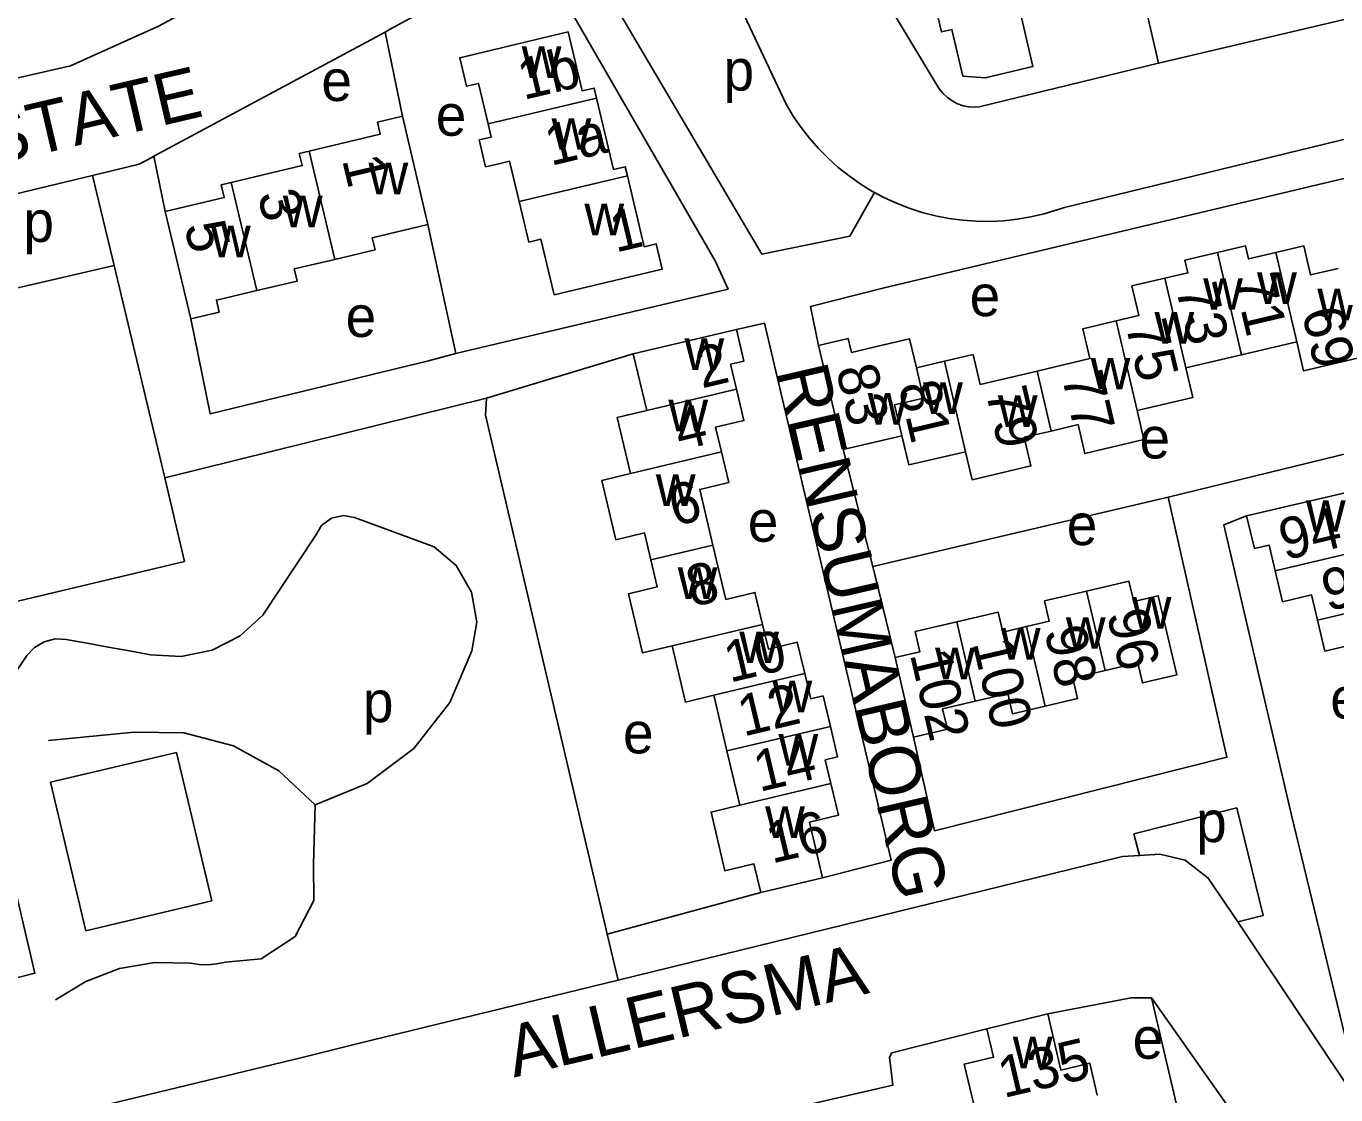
# Model space of a CAD drawing. Extents: x 157646 to 159241, y 379213 to 381217.
# Drawn here: x 158754.8 to 158882.3, y 380482.4 to 380586.3 of the extents above; entities that cross this region are included whole.
import ezdxf

# ---------------------------------------------------------------- set-up
doc = ezdxf.new("R2010")
doc.units = 0
for name, color, linetype in [('BLT_Basislijn', 7, 'Continuous'), ('BLT_Bebouwing', 7, 'Continuous'), ('BLT_Centroide', 7, 'Continuous'), ('BLT_Huisnummer', 7, 'Continuous'), ('BLT_Huisnummer_ tussenligend', 7, 'Continuous'), ('BLT_Onderverdeling_panden', 7, 'Continuous'), ('BLT_Straatnaam', 7, 'Continuous')]:
    doc.layers.add(name, color=color, linetype=linetype)

msp = doc.modelspace()

# ---------------------------------------------------------------- linework, layer by layer
at = {"layer": 'BLT_Basislijn'}
for p, q in [((158828.79, 380578.74), (158821.62, 380593.98)), ((158865.01, 380582.73), (158887.56, 380588.05)), ((158789.75, 380585.76), (158767.26, 380573.68)), ((158789.75, 380585.76), (158791.44, 380577.57)), ((158865.01, 380582.73), (158847.58, 380578.48)), ((158908.94, 380581.61), (158855.86, 380568.7)), ((158767.26, 380573.68), (158768.36, 380568.31)), ((158761.3, 380571.81), (158748.6, 380568.78)), ((158763.38, 380563.06), (158761.3, 380571.81)), ((158834.97, 380565.9), (158837.37, 380570.17)), ((158796.65, 380554.49), (158793.93, 380567.05)), ((158772.74, 380548.64), (158770.84, 380557.88)), ((158793.99, 380553.8), (158796.65, 380554.49)), ((158772.74, 380548.64), (158793.99, 380553.8)), ((158768.31, 380542.39), (158799.61, 380550.17)), ((158834.33, 380545.16), (158837.23, 380533.77)), ((158865.95, 380540.53), (158837.23, 380533.77)), ((158794.53, 380535.7), (158786.78, 380538.55)), ((158783.01, 380536.84), (158777.86, 380529.05)), ((158735.74, 380526.08), (158770.24, 380534.28)), ((158839.38, 380524.92), (158837.23, 380533.77)), ((158754.91, 380525.13), (158751.87, 380520.64)), ((158765.33, 380517.67), (158757, 380516.87)), ((158757.21, 380512.79), (158769.45, 380515.7)), ((158769.45, 380515.7), (158772.88, 380501.25)), ((158760.64, 380498.34), (158757.21, 380512.79)), ((158782.78, 380504.78), (158782.94, 380510.6)), ((158812.44, 380493.55), (158861.52, 380505.56)), ((158826.31, 380502.07), (158811.36, 380498.03)), ((158772.88, 380501.25), (158760.64, 380498.34)), ((158812.44, 380493.55), (158811.36, 380498.03)), ((158812.44, 380493.55), (158787.15, 380487.38)), ((158881.56, 380467.45), (158864.35, 380491.83)), ((158864.35, 380491.83), (158877.59, 380434.98)), ((158781.68, 380486.03), (158787.15, 380487.38)), ((158781.68, 380486.03), (158752.06, 380478.89))]:
    msp.add_line(p, q, dxfattribs=at)
for points in [[(158847.99, 380642.51), (158853.13, 380619.97), (158853.7, 380619.46), (158856.31, 380619.62), (158856.63, 380619.17), (158865.01, 380582.73)], [(158843.68, 380580.23), (158836.93, 380591.46), (158812.34, 380634.13)], [(158808.08, 380595.95), (158810.05, 380591.95), (158826.43, 380564.16), (158834.97, 380565.9)], [(158779.89, 380592.86), (158767.64, 380586.29), (158759.13, 380582.49), (158750.6, 380580.52)], [(158804.41, 380593.74), (158790.19, 380586), (158789.75, 380585.76)], [(158796.65, 380554.49), (158797.44, 380554.69), (158823.13, 380560.77), (158821.88, 380563.52), (158804.41, 380593.74)], [(158843.68, 380580.23), (158844.05, 380579.78), (158844.48, 380579.39), (158844.95, 380579.06), (158845.47, 380578.79), (158846.02, 380578.6), (158846.59, 380578.49), (158847.17, 380578.46), (158847.58, 380578.48)], [(158828.79, 380578.74), (158829.47, 380577.59), (158830.23, 380576.49), (158831.04, 380575.44), (158831.92, 380574.43), (158832.86, 380573.49), (158833.85, 380572.6), (158834.9, 380571.77), (158835.99, 380571), (158837.13, 380570.3), (158837.37, 380570.17)], [(158838.2, 380560.85), (158907.85, 380577.41), (158908.19, 380577.48)], [(158767.26, 380573.68), (158766.98, 380573.52), (158765.83, 380572.92), (158761.3, 380571.81)], [(158837.37, 380570.17), (158838.3, 380569.67), (158839.51, 380569.11), (158840.76, 380568.63), (158842.03, 380568.22), (158843.32, 380567.89), (158844.63, 380567.63), (158845.95, 380567.46), (158847.28, 380567.36), (158848.62, 380567.35), (158849.95, 380567.41), (158851.27, 380567.55), (158852.59, 380567.78), (158853.89, 380568.08), (158855.17, 380568.46), (158855.86, 380568.7)], [(158749.52, 380565.12), (158750.77, 380560.13), (158763.38, 380563.06)], [(158865.95, 380540.53), (158914.06, 380552.25), (158911.37, 380563.45)], [(158768.31, 380542.39), (158763.38, 380563.06)], [(158838.2, 380560.85), (158831.14, 380559.08), (158831.94, 380555.28)], [(158823.94, 380556.84), (158826.69, 380557.44), (158839, 380505.22), (158832.32, 380503.5)], [(158799.61, 380550.17), (158813.91, 380554.46)], [(158799.61, 380550.17), (158799.53, 380548.51), (158811.19, 380498.74), (158811.36, 380498.03)], [(158770.24, 380534.28), (158768.31, 380542.39)], [(158841.19, 380517.19), (158843.21, 380508.08), (158871.68, 380515.22), (158865.95, 380540.53)], [(158783.01, 380536.84), (158783.58, 380537.77), (158784.54, 380538.47), (158785.7, 380538.73), (158786.78, 380538.55)], [(158873.59, 380538.7), (158871.38, 380537.85), (158877.97, 380509.59)], [(158794.53, 380535.7), (158796.68, 380533.88), (158798.18, 380531.3), (158798.69, 380528.36), (158798.21, 380525.58)], [(158766.93, 380525.2), (158769.9, 380525.02), (158772.92, 380525.65), (158775.66, 380527.05), (158777.86, 380529.05)], [(158758.71, 380526.68), (158757.66, 380526.73), (158756.59, 380526.46), (158755.63, 380525.9), (158754.91, 380525.13)], [(158766.93, 380525.2), (158764.87, 380525.57), (158762.82, 380525.94), (158760.77, 380526.31), (158758.71, 380526.68)], [(158798.21, 380525.58), (158796.04, 380520.55), (158792.55, 380516.09), (158788.02, 380512.68), (158782.94, 380510.6)], [(158765.33, 380517.67), (158770.18, 380517.61), (158775.02, 380516.34), (158779.4, 380513.91), (158782.94, 380510.6)], [(158863.15, 380505.67), (158862.63, 380507.79), (158872.65, 380510.3)], [(158872.65, 380510.3), (158875.19, 380499.82), (158872.72, 380499.22)], [(158877.97, 380509.59), (158884.88, 380481.07)], [(158782.78, 380504.78), (158782.81, 380501.29), (158780.99, 380497.79), (158777.69, 380495.63), (158774.22, 380495.3)], [(158863.15, 380505.67), (158861.52, 380505.56)], [(158872.72, 380499.22), (158869.86, 380503.48), (158867.62, 380505.22), (158865.15, 380505.8), (158863.15, 380505.67)], [(158884.88, 380481.07), (158872.72, 380499.22)], [(158770.81, 380495.2), (158767.36, 380495.26), (158763.91, 380494.67), (158760.63, 380493.43), (158757.69, 380491.64)], [(158770.81, 380495.2), (158771.66, 380495.07), (158772.52, 380495.05), (158773.38, 380495.13), (158774.22, 380495.3)], [(158864.35, 380491.83), (158862.34, 380491.84), (158854.23, 380490.27)], [(158848.32, 380488.8), (158839.06, 380486.47), (158838.85, 380486.04), (158839.17, 380483.32), (158797.52, 380473.73)]]:
    msp.add_lwpolyline(points, dxfattribs=at)
at = {"layer": 'BLT_Bebouwing'}
for p, q in [((158791.44, 380577.57), (158793.93, 380567.05)), ((158770.84, 380557.88), (158768.36, 380568.31)), ((158823.94, 380556.84), (158813.91, 380554.46)), ((158878.47, 380555.62), (158873.08, 380554.36)), ((158813.91, 380554.46), (158815.21, 380548.96)), ((158834.33, 380545.16), (158831.94, 380555.28)), ((158873.08, 380554.36), (158867.69, 380553.09)), ((158841.19, 380517.19), (158839.38, 380524.92)), ((158821.74, 380521.26), (158823.02, 380515.84)), ((158823.02, 380515.84), (158824.27, 380510.57)), ((158826.31, 380502.07), (158832.32, 380503.5)), ((158854.23, 380490.27), (158848.32, 380488.8))]:
    msp.add_line(p, q, dxfattribs=at)
for points in [[(158842.44, 380591.96), (158843.89, 380585.78), (158844.92, 380586.03), (158845.99, 380581.47), (158848.15, 380581.31), (158852.79, 380582.41), (158851.58, 380587.59), (158852.67, 380587.84), (158851.64, 380592.22), (158856.45, 380593.36), (158858.4, 380593.82), (158859.43, 380589.46), (158862.31, 380590.15), (158860.85, 380596.29), (158856.03, 380595.15)], [(158810.32, 380579.35), (158810.09, 380580.32), (158808.93, 380580.05), (158807.57, 380585.78), (158797.02, 380583.27), (158797.68, 380580.49), (158798.85, 380580.77), (158799.78, 380576.85)], [(158813.35, 380571.77), (158813.13, 380572.67), (158811.97, 380572.4), (158810.32, 380579.35)], [(158782.36, 380574.17), (158789.29, 380575.82), (158789.01, 380577), (158791.44, 380577.57)], [(158799.78, 380576.85), (158800.09, 380575.55), (158798.92, 380575.27), (158799.54, 380572.66), (158800.71, 380572.93), (158801.87, 380573.21), (158802.8, 380569.27)], [(158774.78, 380571.13), (158781.69, 380572.77), (158781.41, 380573.95), (158782.36, 380574.17)], [(158768.36, 380568.31), (158774.1, 380569.67), (158773.81, 380570.9), (158774.78, 380571.13)], [(158802.8, 380569.27), (158803.74, 380565.34), (158804.92, 380565.62), (158806.2, 380560.22), (158816.72, 380562.71), (158816.14, 380565.16), (158814.98, 380564.89), (158813.35, 380571.77)], [(158793.93, 380567.05), (158788.51, 380565.76), (158788.79, 380564.59), (158784.86, 380563.65)], [(158870.74, 380564.32), (158873.47, 380564.96), (158873.76, 380563.7), (158876.43, 380564.33)], [(158876.43, 380564.33), (158879.16, 380564.97), (158879.81, 380562.15), (158882.49, 380562.78)], [(158784.86, 380563.65), (158780.92, 380562.72), (158781.2, 380561.55), (158777.27, 380560.62)], [(158865.64, 380561.82), (158867.88, 380562.34), (158867.59, 380563.59), (158870.74, 380564.32)], [(158860.9, 380557.67), (158863.1, 380558.18), (158862.43, 380561.07), (158865.64, 380561.82)], [(158777.27, 380560.62), (158773.34, 380559.69), (158773.61, 380558.53), (158770.84, 380557.88)], [(158823.94, 380551.03), (158823.37, 380553.45), (158824.67, 380553.76), (158823.94, 380556.84)], [(158853.21, 380552.79), (158858.34, 380554), (158857.66, 380556.91), (158860.9, 380557.67)], [(158831.94, 380555.28), (158834.81, 380555.96), (158835.13, 380554.6), (158837.99, 380555.27)], [(158837.99, 380555.27), (158840.8, 380555.93), (158841.46, 380553.11)], [(158884.52, 380554.08), (158879.12, 380552.82), (158878.47, 380555.62)], [(158844.18, 380553.75), (158846.98, 380554.4), (158847.66, 380551.49), (158853.21, 380552.79)], [(158841.46, 380553.11), (158844.18, 380553.75)], [(158867.69, 380553.09), (158868.36, 380550.22), (158862.94, 380548.95)], [(158822.48, 380544.92), (158821.91, 380547.32), (158824.67, 380547.97), (158823.94, 380551.03)], [(158815.21, 380548.96), (158812.33, 380548.27), (158813.62, 380542.82)], [(158862.94, 380548.95), (158863.6, 380546.12), (158857.85, 380544.77), (158857.19, 380547.58), (158854.57, 380546.96)], [(158854.57, 380546.96), (158851.95, 380546.35), (158852.6, 380543.57), (158846.88, 380542.22), (158846.24, 380544.95)], [(158840.71, 380543.66), (158840.04, 380546.5), (158834.33, 380545.16)], [(158821.66, 380535.85), (158820.38, 380541.28), (158823.19, 380541.94), (158822.48, 380544.92)], [(158846.24, 380544.95), (158840.71, 380543.66)], [(158813.62, 380542.82), (158810.84, 380542.16), (158812.21, 380536.38), (158815, 380537.04), (158815.62, 380534.42)], [(158886.63, 380541.42), (158883.81, 380540.76), (158883.73, 380541.08), (158873.59, 380538.7)], [(158873.59, 380538.7), (158874.36, 380535.52), (158875.78, 380535.86), (158876.38, 380533.36)], [(158826.49, 380528.14), (158825.75, 380531.26), (158822.91, 380530.58), (158821.66, 380535.85)], [(158815.62, 380534.42), (158816.24, 380531.79), (158813.44, 380531.13), (158814.8, 380525.37), (158817.69, 380526.05)], [(158876.38, 380533.36), (158877.09, 380530.35), (158879.91, 380531.02), (158880.49, 380528.57)], [(158852.16, 380527.94), (158854.38, 380528.46), (158853.92, 380530.43), (158858.02, 380531.39)], [(158858.02, 380531.39), (158862.14, 380532.36), (158862.6, 380530.37), (158864.99, 380530.93), (158866.79, 380523.24), (158863.45, 380522.46), (158862.99, 380524.41), (158859.83, 380523.67)], [(158845.38, 380528.4), (158849.41, 380529.34), (158849.86, 380527.4), (158852.16, 380527.94)], [(158830.59, 380523.36), (158829.87, 380526.42), (158827.05, 380525.75), (158826.49, 380528.14)], [(158839.38, 380524.92), (158841.8, 380525.49), (158841.34, 380527.45), (158845.38, 380528.4)], [(158880.49, 380528.57), (158881.2, 380525.56), (158884.08, 380526.24), (158885.34, 380520.91)], [(158817.69, 380526.05), (158818.98, 380520.6), (158821.74, 380521.26)], [(158833.09, 380518.23), (158832.38, 380521.2), (158831.17, 380520.91), (158830.59, 380523.36)], [(158859.83, 380523.67), (158856.67, 380522.93), (158857.14, 380520.93), (158853.98, 380520.19)], [(158853.98, 380520.19), (158850.82, 380519.45), (158850.36, 380521.43), (158847.18, 380520.69)], [(158847.18, 380520.69), (158844.01, 380519.94), (158844.47, 380517.96), (158841.19, 380517.19)], [(158833.12, 380512.67), (158832.58, 380514.97), (158833.79, 380515.26), (158833.09, 380518.23)], [(158743.74, 380514.12), (158745.39, 380507.15), (158752.24, 380508.77), (158755.67, 380494.22), (158750.2, 380492.82), (158750.89, 380489.95), (158749.6, 380489.64)], [(158832.32, 380503.5), (158831.04, 380508.91), (158833.86, 380509.58), (158833.12, 380512.67)], [(158824.27, 380510.57), (158821.47, 380509.9), (158822.83, 380504.19), (158825.65, 380504.86), (158826.31, 380502.07)], [(158859.05, 380482.36), (158858.33, 380485.46), (158855.5, 380484.8), (158854.23, 380490.27)], [(158848.32, 380488.8), (158848.96, 380486.05), (158846.12, 380485.39), (158847.26, 380480.52), (158847.46, 380479.65), (158850.32, 380480.32)]]:
    msp.add_lwpolyline(points, dxfattribs=at)
at = {"layer": 'BLT_Onderverdeling_panden'}
for p, q in [((158799.78, 380576.85), (158810.32, 380579.35)), ((158784.86, 380563.65), (158782.36, 380574.17)), ((158777.27, 380560.62), (158774.78, 380571.13)), ((158802.8, 380569.27), (158813.35, 380571.77)), ((158873.08, 380554.36), (158870.74, 380564.32)), ((158878.47, 380555.62), (158876.43, 380564.33)), ((158867.69, 380553.09), (158865.64, 380561.82)), ((158862.94, 380548.95), (158860.9, 380557.67)), ((158846.24, 380544.95), (158844.18, 380553.75)), ((158854.57, 380546.96), (158853.21, 380552.79)), ((158815.21, 380548.96), (158823.94, 380551.03)), ((158813.62, 380542.82), (158822.48, 380544.92)), ((158815.62, 380534.42), (158821.66, 380535.85)), ((158876.38, 380533.36), (158887.88, 380536.08)), ((158859.83, 380523.67), (158858.02, 380531.39)), ((158880.49, 380528.57), (158889.17, 380530.62)), ((158817.69, 380526.05), (158826.49, 380528.14)), ((158847.18, 380520.69), (158845.38, 380528.4)), ((158853.98, 380520.19), (158852.16, 380527.94)), ((158821.74, 380521.26), (158830.59, 380523.36)), ((158833.09, 380518.23), (158823.02, 380515.84)), ((158824.27, 380510.57), (158833.12, 380512.67))]:
    msp.add_line(p, q, dxfattribs=at)
msp.add_lwpolyline([(158840.71, 380543.66), (158839.34, 380549.51), (158842.14, 380550.17), (158841.46, 380553.11)], dxfattribs=at)

# ---------------------------------------------------------------- texts
at = {"layer": 'BLT_Centroide'}
for s, p in [('w', (158803.05, 380581.31)), ('p', (158822.69, 380580.07)), ('e', (158783.56, 380579.06)), ('e', (158794.69, 380575.68)), ('w', (158805.95, 380574.31)), ('w', (158788.14, 380569.98)), ('w', (158779.81, 380566.77)), ('p', (158754.56, 380565.35)), ('w', (158809.15, 380566)), ('w', (158772.81, 380563.86)), ('w', (158874.61, 380559.31)), ('e', (158846.64, 380558.13)), ('w', (158869.36, 380558.75)), ('w', (158880.47, 380557.72)), ('e', (158785.92, 380556.11)), ('w', (158864.62, 380555.47)), ('w', (158818.89, 380552.91)), ('w', (158858.41, 380551)), ('w', (158836.72, 380547.59)), ('w', (158842.11, 380548.62)), ('w', (158817.32, 380546.94)), ('w', (158849.38, 380547.36)), ('e', (158863.17, 380544.29)), ('w', (158816.1, 380539.66)), ('e', (158825.05, 380536.19)), ('e', (158856.09, 380535.86)), ('w', (158879.36, 380537.16)), ('w', (158818.23, 380530.62)), ('w', (158862.41, 380527.75)), ('w', (158856, 380525.78)), ('w', (158849.67, 380524.73)), ('w', (158824.22, 380524.38)), ('w', (158843.28, 380522.8)), ('w', (158827.45, 380519.59)), ('p', (158787.6, 380518.64)), ('e', (158881.73, 380518.98)), ('e', (158812.91, 380515.6)), ('w', (158828.04, 380514.41)), ('w', (158826.74, 380507.38)), ('p', (158868.68, 380506.97)), ('w', (158850.84, 380484.97)), ('e', (158862.5, 380485.9))]:
    msp.add_text(s, height=4, dxfattribs=at).set_placement(p)
at = {"layer": 'BLT_Huisnummer'}
for s, rotation, p in [('1b', 13.341, (158803.22, 380579.15)), ('1a', 13.341, (158805.87, 380572.74)), ('1', 283.3412, (158785.56, 380573.35)), ('1', 13.341, (158812.18, 380564.3)), ('5', 283.3405, (158770.19, 380566.92)), ('73', 283.1845, (158866.68, 380560.87)), ('69', 283.1845, (158878.94, 380558.56)), ('2', 13.3437, (158820.57, 380551.09)), ('83', 283.1845, (158833.61, 380552.99)), ('77', 283.1845, (158855.58, 380552.28)), ('6', 13.3437, (158817.91, 380537.69)), ('94', 13.2523, (158877.29, 380534.38)), ('96', 283.1828, (158859.96, 380529.18)), ('10', 13.3437, (158823.29, 380522.47)), ('102', 283.1827, (158840.81, 380525.26)), ('16', 13.3437, (158827.39, 380504.88)), ('135', 13.1646, (158849.94, 380482.07))]:
    msp.add_text(s, height=4, rotation=rotation, dxfattribs=at).set_placement(p)
at = {"layer": 'BLT_Huisnummer_ tussenligend'}
for s, rotation, p in [('3', 283.3412, (158777.33, 380569.98)), ('71', 283.1845, (158872.31, 380561.77)), ('75', 283.1845, (158861.79, 380557.31)), ('81', 283.1845, (158839.68, 380551.39)), ('79', 283.1845, (158848.18, 380550.79)), ('4', 13.3437, (158818.46, 380545.05)), ('8', 13.3437, (158819.62, 380529.82)), ('92', 13.2523, (158881.45, 380529.41)), ('98', 283.1828, (158853.89, 380527.54)), ('100', 283.1828, (158846.9, 380526.36)), ('12', 13.3437, (158824.62, 380517.23)), ('14', 13.3437, (158826.17, 380511.84))]:
    msp.add_text(s, height=4, rotation=rotation, dxfattribs=at).set_placement(p)
at = {"layer": 'BLT_Straatnaam'}
for s, rotation, p in [('JONGEMASTATE', 13.1456, (158719.05, 380565.2)), ('RENSUMABORG', 283.0047, (158827.83, 380552.83)), ('ALLERSMA', 13.3541, (158802.29, 380484.07))]:
    msp.add_text(s, height=5, rotation=rotation, dxfattribs=at).set_placement(p)

doc.saveas('drawing.dxf')
